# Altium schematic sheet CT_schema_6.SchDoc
size 254 x 194 mm
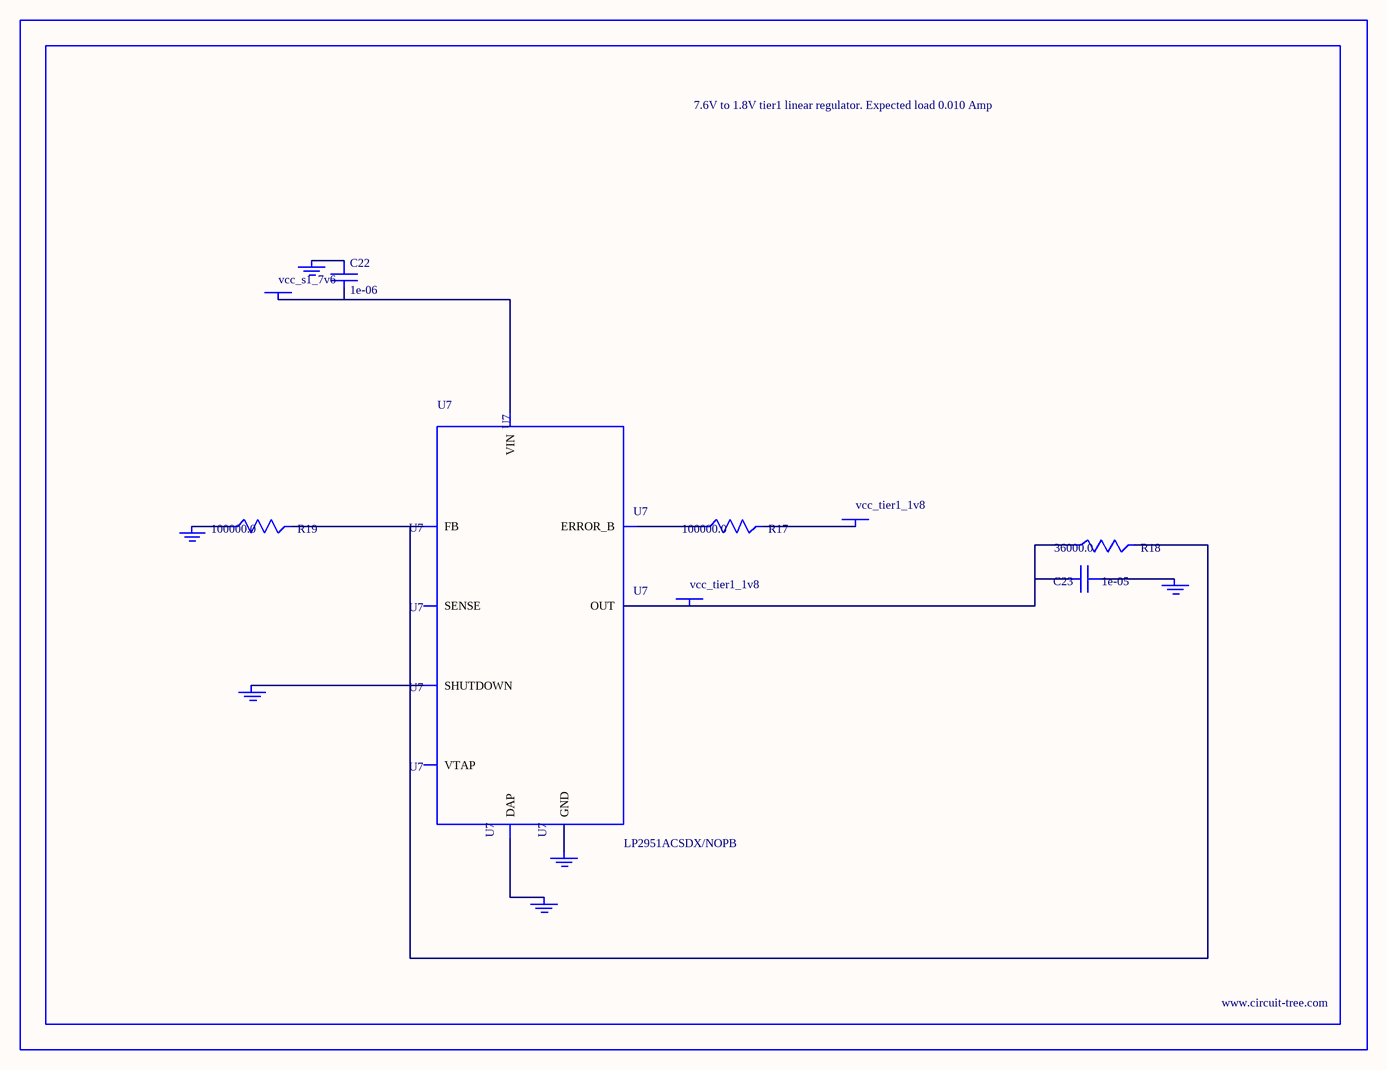
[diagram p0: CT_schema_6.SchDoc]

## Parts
BORDER5  (no value)
C22  1e-06  [C0603]
C23  1e-05  [C0805]
GND_INSTANCE_5_0  (no value)
GND_INSTANCE_5_1  (no value)
GND_INSTANCE_5_2  (no value)
GND_INSTANCE_5_3  (no value)
GND_INSTANCE_5_4  (no value)
GND_INSTANCE_5_5  (no value)
POWER_INSTANCE_5_0  vcc_tier1_1v8
POWER_INSTANCE_5_1  vcc_s1_7v6
POWER_INSTANCE_5_2  vcc_tier1_1v8
R17  100000.0  [R0603]
R18  36000.0  [R0603]
R19  100000.0  [R0603]
U7  LP2951ACSDX/NOPB  [WSON-8]

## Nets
NetC22_1: C22.1 GND_INSTANCE_5_3.0(GND)
NetC22_2: C22.2 POWER_INSTANCE_5_1.0(PWR) U7.8(VIN)
NetC23_1: C23.1 GND_INSTANCE_5_0.0(GND)
NetC23_2: C23.2 POWER_INSTANCE_5_2.0(PWR) R18.1 U7.1(OUT)
NetGND_INSTANCE_5_1_0: GND_INSTANCE_5_1.0(GND) U7.3(SHUTDOWN)
NetGND_INSTANCE_5_2_0: GND_INSTANCE_5_2.0(GND) R19.1
NetGND_INSTANCE_5_4_0: GND_INSTANCE_5_4.0(GND) U7.PAD(DAP)
NetGND_INSTANCE_5_5_0: GND_INSTANCE_5_5.0(GND) U7.4(GND)
NetPOWER_INSTANCE_5_0_0: POWER_INSTANCE_5_0.0(PWR) R17.2
NetR17_1: R17.1 U7.5(ERROR_B)
NetR18_2: R18.2 R19.2 U7.7(FB)

Not connected (* = marked no-connect by the designer): U7 2(SENSE) 6(VTAP)

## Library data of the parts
BORDER5 = BORDER_PAGE5
C22 = C0603C105K3RACTU
C23 = GRM219R60J106ME19D
GND_INSTANCE_5_0-GND_INSTANCE_5_5 = GND
POWER_INSTANCE_5_0-POWER_INSTANCE_5_2 = PWR
R17 R19 = RC0603JR-07100KL
R18 = RC0603JR-0736KL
